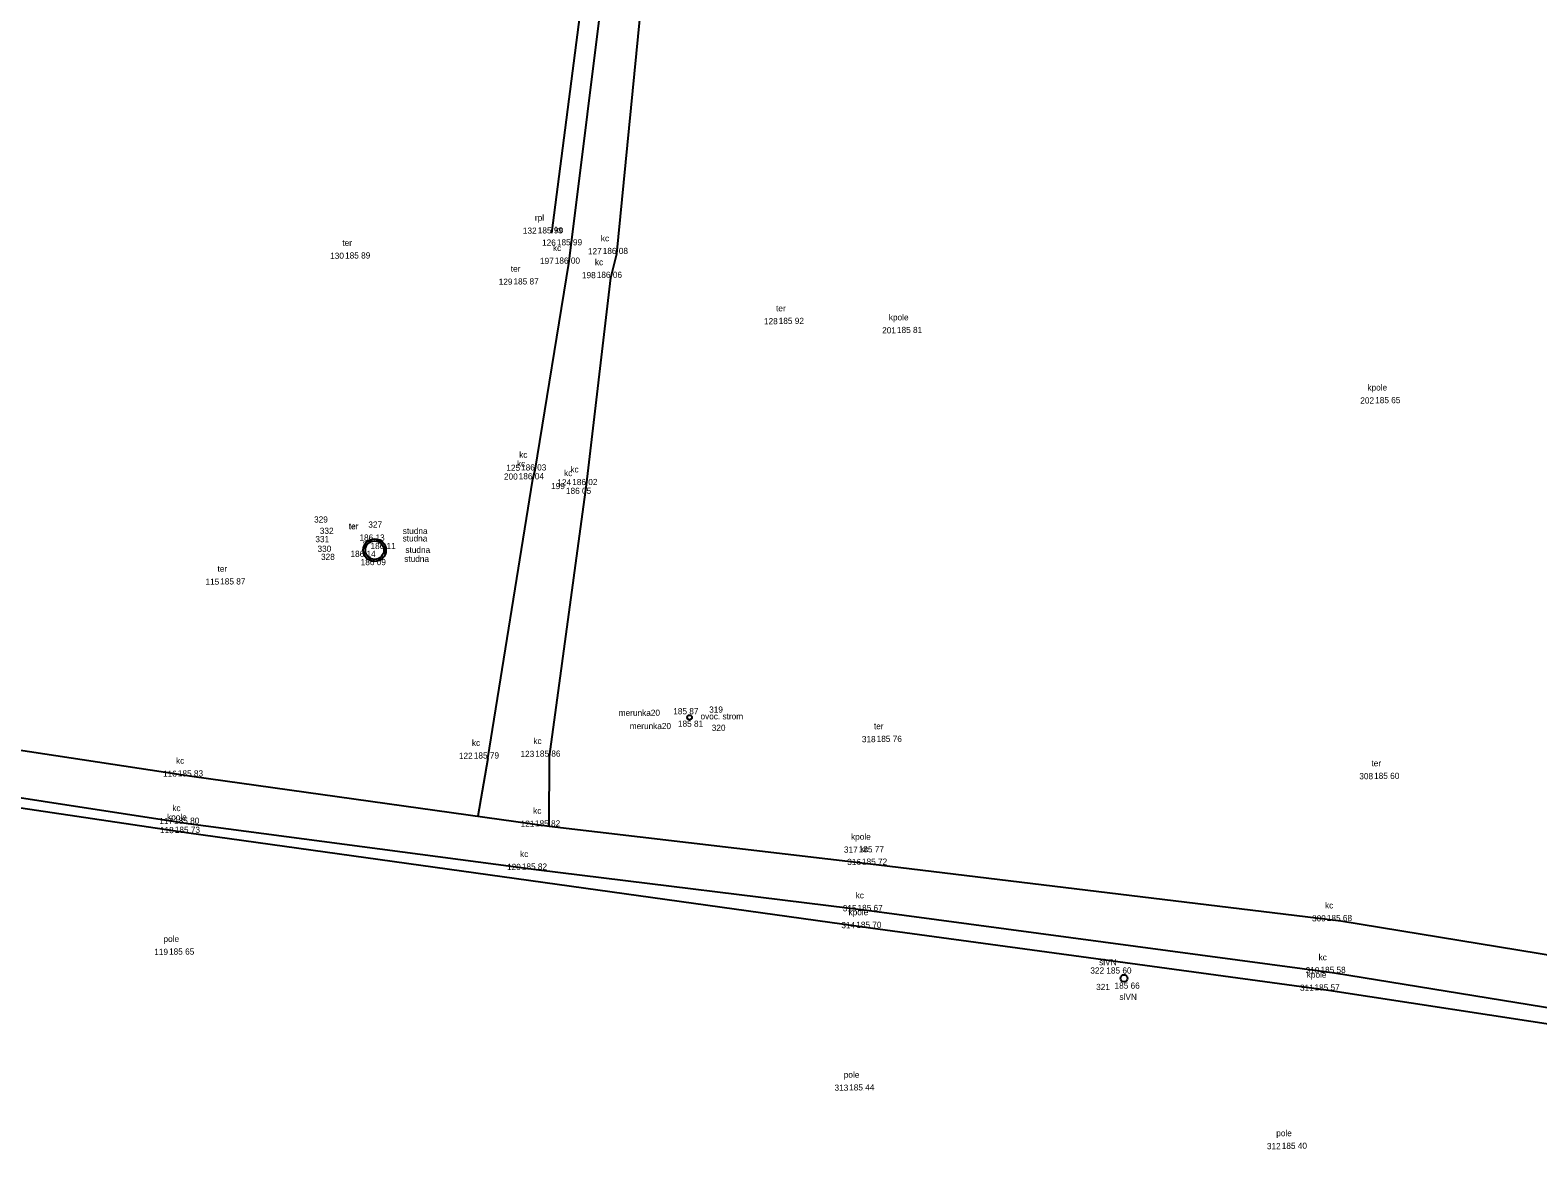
# Model space of a CAD drawing. Extents: x -598527 to -598215, y -1172822 to -1172560.
# Drawn here: x -598390 to -598316.7, y -1172714.5 to -1172658.9 of the extents above; entities that cross this region are included whole.
import ezdxf

# ---------------------------------------------------------------- set-up
doc = ezdxf.new("R2010")
doc.units = 0
for name, color, linetype in [('Body', 7, 'Continuous'), ('Body čísla', 7, 'Continuous'), ('Kody', 7, 'Continuous'), ('Kraj pole', 7, 'Continuous'), ('PATTERN_CLASS', 7, 'Continuous'), ('Ploty', 7, 'Continuous'), ('Sachty', 7, 'Continuous'), ('Stromy', 7, 'Continuous'), ('Výšky', 7, 'Continuous')]:
    doc.layers.add(name, color=color, linetype=linetype)

msp = doc.modelspace()

# ---------------------------------------------------------------- linework, layer by layer
at = {"layer": 'Body'}
for p, q in [((-598364.62, -1172668.75), (-598364.62, -1172668.75)), ((-598363.69, -1172669.33), (-598363.69, -1172669.33)), ((-598373.99, -1172669.97), (-598373.99, -1172669.97)), ((-598361.46, -1172669.75), (-598361.46, -1172669.75)), ((-598363.79, -1172670.22), (-598363.79, -1172670.22)), ((-598365.8, -1172671.23), (-598365.8, -1172671.23)), ((-598361.75, -1172670.91), (-598361.75, -1172670.91)), ((-598352.9, -1172673.15), (-598352.9, -1172673.15)), ((-598347.17, -1172673.59), (-598347.17, -1172673.59)), ((-598323.9, -1172677), (-598323.9, -1172677)), ((-598365.43, -1172680.27), (-598365.43, -1172680.27)), ((-598365.54, -1172680.7), (-598365.54, -1172680.7)), ((-598362.94, -1172680.98), (-598362.94, -1172680.98)), ((-598363.25, -1172681.16), (-598363.25, -1172681.16)), ((-598373.68, -1172683.75), (-598373.68, -1172683.75)), ((-598373.67, -1172683.74), (-598373.67, -1172683.74)), ((-598373.29, -1172683.7), (-598373.29, -1172683.7)), ((-598373.72, -1172684.13), (-598373.72, -1172684.13)), ((-598373.23, -1172684.6), (-598373.23, -1172684.6)), ((-598372.77, -1172684.09), (-598372.77, -1172684.09)), ((-598380.06, -1172685.81), (-598380.06, -1172685.81)), ((-598358.03, -1172692.23), (-598358.03, -1172692.23)), ((-598357.82, -1172692.32), (-598357.82, -1172692.32)), ((-598348.14, -1172693.46), (-598348.14, -1172693.46)), ((-598367.73, -1172694.27), (-598367.73, -1172694.27)), ((-598364.74, -1172694.18), (-598364.74, -1172694.18)), ((-598382.12, -1172695.14), (-598382.12, -1172695.14)), ((-598323.95, -1172695.26), (-598323.95, -1172695.26)), ((-598382.3, -1172697.44), (-598382.3, -1172697.44)), ((-598382.27, -1172697.88), (-598382.27, -1172697.88)), ((-598364.75, -1172697.57), (-598364.75, -1172697.57)), ((-598349.01, -1172698.83), (-598349.01, -1172698.83)), ((-598348.85, -1172699.43), (-598348.85, -1172699.43)), ((-598365.39, -1172699.67), (-598365.39, -1172699.67)), ((-598349.07, -1172701.68), (-598349.07, -1172701.68)), ((-598326.25, -1172702.17), (-598326.25, -1172702.17)), ((-598349.13, -1172702.5), (-598349.13, -1172702.5)), ((-598382.55, -1172703.8), (-598382.55, -1172703.8)), ((-598336.97, -1172704.93), (-598336.97, -1172704.93)), ((-598336.63, -1172704.97), (-598336.63, -1172704.97)), ((-598326.56, -1172704.69), (-598326.56, -1172704.69)), ((-598326.85, -1172705.54), (-598326.85, -1172705.54)), ((-598349.47, -1172710.4), (-598349.47, -1172710.4)), ((-598328.44, -1172713.24), (-598328.44, -1172713.24))]:
    msp.add_line(p, q, dxfattribs=at)
at = {"layer": 'Kraj pole'}
for p, q in [((-598382.27, -1172697.88), (-598349.13, -1172702.5)), ((-598349.13, -1172702.5), (-598326.85, -1172705.54))]:
    msp.add_line(p, q, dxfattribs=at)
at = {"layer": 'PATTERN_CLASS'}
msp.add_line((-598367.73, -1172694.27), (-598368.228, -1172697.084), dxfattribs=at)
for points in [[(-598364.75, -1172697.57), (-598364.74, -1172694.18), (-598362.94, -1172680.98), (-598361.75, -1172670.91), (-598361.46, -1172669.75), (-598360.16, -1172656.53), (-598359.41, -1172647.34), (-598358.97, -1172644.52), (-598357.622, -1172635.884), (-598355.54, -1172619.61), (-598354.53, -1172610.23), (-598352.51, -1172595.34), (-598351.22, -1172585.21), (-598348.76, -1172585.57), (-598347.59, -1172581.3), (-598346.856, -1172579.801), (-598345.8, -1172578.12), (-598344.503, -1172576.902), (-598343.57, -1172576.22)], [(-598367.73, -1172694.27), (-598365.54, -1172680.7), (-598365.43, -1172680.27), (-598363.79, -1172670.22), (-598363.69, -1172669.33), (-598362.1, -1172656.58), (-598361.21, -1172647.28), (-598360.79, -1172644.02), (-598359.76, -1172635.59), (-598357.41, -1172619.26), (-598356.18, -1172609.95), (-598354.7, -1172595.04), (-598353.57, -1172584.71)], [(-598492.58, -1172680.02), (-598468.55, -1172682.91), (-598441.63, -1172686.62), (-598421.91, -1172689.41), (-598395.91, -1172693.05), (-598382.12, -1172695.14), (-598364.75, -1172697.57), (-598348.85, -1172699.43), (-598326.25, -1172702.17), (-598291.63, -1172707.83), (-598276.21, -1172710.42), (-598272.67, -1172710.2), (-598270.07, -1172709.11), (-598268.17, -1172706.75)], [(-598504.27, -1172686.48), (-598502.86, -1172683.29), (-598501.21, -1172681.85), (-598498.91, -1172681.7), (-598493.15, -1172682.35), (-598468.61, -1172685.05), (-598441.9, -1172688.98), (-598422.43, -1172691.66), (-598396.42, -1172695.27), (-598382.3, -1172697.44), (-598365.39, -1172699.67), (-598349.07, -1172701.68), (-598326.56, -1172704.69), (-598292, -1172710.32), (-598276.32, -1172712.66), (-598273.75, -1172712.88), (-598270.71, -1172712.27), (-598268.64, -1172711.13), (-598269.17, -1172714.46)]]:
    msp.add_lwpolyline(points, dxfattribs=at)
msp.add_circle((-598336.8, -1172704.953), 0.171, dxfattribs=at)
at = {"layer": 'Ploty'}
for p, q in [((-598364.62, -1172668.75), (-598362.72, -1172654.07)), ((-598396.57, -1172695.76), (-598382.27, -1172697.88)), ((-598326.85, -1172705.54), (-598292.74, -1172710.77))]:
    msp.add_line(p, q, dxfattribs=at)
at = {"layer": 'Sachty'}
for radius in [0.551, 0.451]:
    msp.add_circle((-598373.24, -1172684.149), radius, dxfattribs=at)
at = {"layer": 'Stromy'}
msp.add_circle((-598357.927, -1172692.279), 0.114, dxfattribs=at)

# ---------------------------------------------------------------- texts
at = {"layer": 'Body čísla'}
for s, p in [('132', (-598366.031, -1172668.773)), ('126', (-598365.097, -1172669.353)), ('130', (-598375.4, -1172669.993)), ('197', (-598365.198, -1172670.243)), ('127', (-598362.868, -1172669.773)), ('198', (-598363.158, -1172670.933)), ('129', (-598367.206, -1172671.253)), ('128', (-598354.308, -1172673.173)), ('201', (-598348.561, -1172673.613)), ('202', (-598325.311, -1172677.023)), ('125', (-598366.835, -1172680.293)), ('200', (-598366.95, -1172680.723)), ('199', (-598364.656, -1172681.183)), ('124', (-598364.354, -1172681.003)), ('329', (-598376.183, -1172682.809)), ('332', (-598375.904, -1172683.36)), ('327', (-598373.546, -1172683.057)), ('331', (-598376.121, -1172683.763)), ('330', (-598376.017, -1172684.233)), ('328', (-598375.845, -1172684.623)), ('115', (-598381.465, -1172685.833)), ('319', (-598356.972, -1172692.048)), ('320', (-598356.846, -1172692.931)), ('318', (-598349.548, -1172693.483)), ('122', (-598369.141, -1172694.293)), ('123', (-598366.147, -1172694.203)), ('116', (-598383.527, -1172695.163)), ('308', (-598325.358, -1172695.283)), ('117', (-598383.708, -1172697.463)), ('118', (-598383.678, -1172697.903)), ('121', (-598366.141, -1172697.593)), ('317', (-598350.418, -1172698.853)), ('120', (-598366.8, -1172699.693)), ('316', (-598350.257, -1172699.453)), ('315', (-598350.475, -1172701.703)), ('314', (-598350.544, -1172702.523)), ('309', (-598327.656, -1172702.193)), ('119', (-598383.956, -1172703.823)), ('322', (-598338.437, -1172704.727)), ('310', (-598327.97, -1172704.713)), ('321', (-598338.155, -1172705.528)), ('311', (-598328.241, -1172705.563)), ('313', (-598350.877, -1172710.423)), ('312', (-598329.851, -1172713.263))]:
    msp.add_text(s, height=0.3, dxfattribs=at).set_placement(p)
at = {"layer": 'Kody'}
for s, p in [('rpl', (-598365.446, -1172668.143)), ('kc', (-598364.468, -1172668.723)), ('ter', (-598374.809, -1172669.363)), ('kc', (-598364.568, -1172669.613)), ('kc', (-598362.238, -1172669.143)), ('kc', (-598362.528, -1172670.303)), ('ter', (-598366.619, -1172670.623)), ('ter', (-598353.719, -1172672.543)), ('kpole', (-598348.234, -1172672.983)), ('kpole', (-598324.964, -1172676.393)), ('kc', (-598366.208, -1172679.663)), ('kc', (-598366.318, -1172680.093)), ('kc', (-598364.028, -1172680.553)), ('kc', (-598363.718, -1172680.373)), ('ter', (-598374.499, -1172683.143)), ('ter', (-598374.489, -1172683.133)), ('studna', (-598371.87, -1172683.367)), ('studna', (-598371.743, -1172684.285)), ('studna', (-598371.799, -1172684.719)), ('ter', (-598380.879, -1172685.203)), ('merunka20', (-598361.37, -1172692.203)), ('merunka20', (-598360.833, -1172692.847)), ('ter', (-598348.959, -1172692.853)), ('kc', (-598368.508, -1172693.663)), ('kc', (-598365.518, -1172693.573)), ('kc', (-598382.898, -1172694.533)), ('ter', (-598324.769, -1172694.653)), ('kc', (-598383.078, -1172696.833)), ('kpole', (-598383.334, -1172697.273)), ('kc', (-598365.528, -1172696.963)), ('kpole', (-598350.074, -1172698.223)), ('kc', (-598349.628, -1172698.823)), ('kc', (-598366.168, -1172699.063)), ('kc', (-598349.848, -1172701.073)), ('kpole', (-598350.194, -1172701.893)), ('kc', (-598327.028, -1172701.563)), ('pole', (-598383.507, -1172703.193)), ('kc', (-598327.338, -1172704.083)), ('slVN', (-598338.009, -1172704.323)), ('kpole', (-598327.914, -1172704.933)), ('pole', (-598350.427, -1172709.793)), ('pole', (-598329.397, -1172712.633))]:
    msp.add_text(s, height=0.3, dxfattribs=at).set_placement(p)
at = {"layer": 'PATTERN_CLASS'}
msp.add_text('slVN', height=0.3, dxfattribs=at).set_placement((-598337.023, -1172706.007))
at = {"layer": 'Sachty'}
msp.add_text('studna', height=0.3, dxfattribs=at).set_placement((-598371.881, -1172683.728))
at = {"layer": 'Stromy'}
msp.add_text('ovoc. strom', height=0.3, dxfattribs=at).set_placement((-598357.394, -1172692.374))
at = {"layer": 'Výšky'}
for s, height, p in [('185 99', 0.3, (-598365.307, -1172668.758)), ('185 99', 0.3, (-598364.377, -1172669.338)), ('185 89', 0.3, (-598374.677, -1172669.978)), ('186 00', 0.3, (-598364.48, -1172670.228)), ('186 08', 0.3, (-598362.148, -1172669.758)), ('186 06', 0.3, (-598362.438, -1172670.918)), ('185 87', 0.3, (-598366.489, -1172671.238)), ('185 92', 0.3, (-598353.591, -1172673.158)), ('185 81', 0.3, (-598347.841, -1172673.598)), ('185 65', 0.3, (-598324.586, -1172677.008)), ('186 04', 0.3, (-598366.234, -1172680.708)), ('186 03', 0.3, (-598366.117, -1172680.278)), ('186 05', 0.3, (-598363.936, -1172681.415)), ('186 02', 0.3, (-598363.631, -1172680.988)), ('186 13', 0.3, (-598373.977, -1172683.688)), ('185 79', 0.0629, (-598373.826, -1172683.821)), ('185 83', 0.0629, (-598373.817, -1172683.751)), ('186 11', 0.3, (-598373.441, -1172684.098)), ('186 14', 0.3, (-598374.414, -1172684.478)), ('186 09', 0.3, (-598373.917, -1172684.88)), ('185 87', 0.3, (-598380.749, -1172685.818)), ('185 87', 0.3, (-598358.719, -1172692.127)), ('185 81', 0.3, (-598358.491, -1172692.734)), ('185 76', 0.3, (-598348.828, -1172693.468)), ('185 79', 0.3, (-598368.417, -1172694.278)), ('185 86', 0.3, (-598365.428, -1172694.188)), ('185 83', 0.3, (-598382.807, -1172695.148)), ('185 60', 0.3, (-598324.64, -1172695.268)), ('185 80', 0.3, (-598382.99, -1172697.448)), ('185 82', 0.3, (-598365.441, -1172697.578)), ('185 73', 0.3, (-598382.957, -1172697.888)), ('185 77', 0.3, (-598349.699, -1172698.838)), ('185 82', 0.3, (-598366.081, -1172699.678)), ('185 72', 0.3, (-598349.541, -1172699.438)), ('185 67', 0.3, (-598349.759, -1172701.688)), ('185 70', 0.3, (-598349.82, -1172702.508)), ('185 68', 0.3, (-598326.938, -1172702.178)), ('185 65', 0.3, (-598383.236, -1172703.808)), ('185 60', 0.3, (-598337.66, -1172704.728)), ('185 58', 0.3, (-598327.248, -1172704.698)), ('185 66', 0.3, (-598337.261, -1172705.462)), ('185 57', 0.3, (-598327.539, -1172705.548)), ('185 44', 0.3, (-598350.164, -1172710.408)), ('185 40', 0.3, (-598329.13, -1172713.248))]:
    msp.add_text(s, height=height, dxfattribs=at).set_placement(p)

doc.saveas('drawing.dxf')
